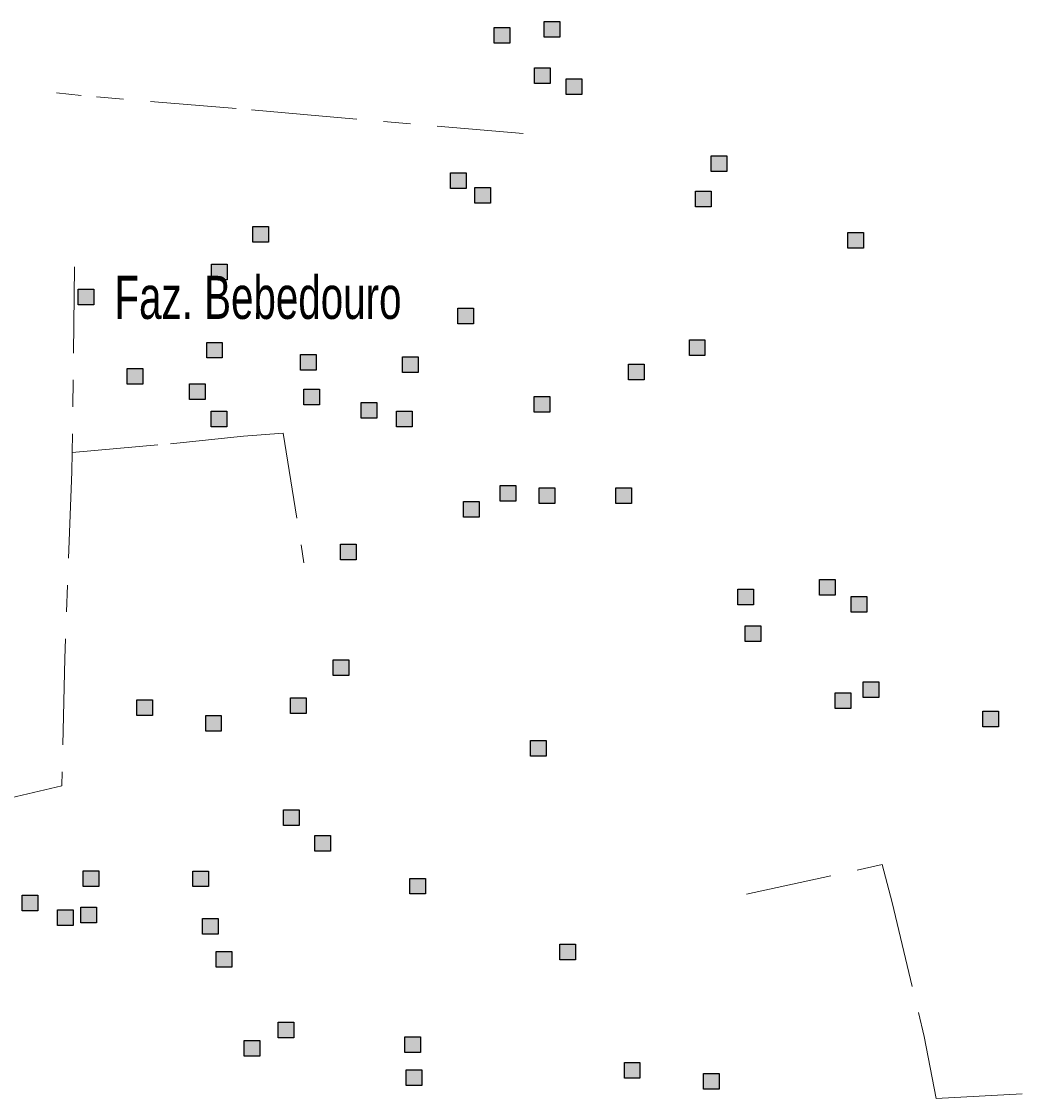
# Model space of a CAD drawing. Extents: x 445.4 to 500, y 8728.7 to 8784.
# Drawn here: x 459.662 to 463.381, y 8743.151 to 8747.148 of the extents above; entities that cross this region are included whole.
import ezdxf

# ---------------------------------------------------------------- set-up
doc = ezdxf.new("R2010")
doc.units = 0
doc.header["$LTSCALE"] = 0.064
doc.linetypes.add('DOT_DASHED', pattern=[7.7, 5, -1.2, 0.3, -1.2])
doc.layers.add('2', color=7, linetype='Continuous', lineweight=25)
doc.layers.add('22', color=7, linetype='DOT_DASHED', lineweight=13)
doc.layers.add('61', color=7, linetype='Continuous')

msp = doc.modelspace()

# ---------------------------------------------------------------- hatches: boundary and pattern name
at = {"layer": '2'}
for points in [[(461.4171, 8747.1256), (461.4751, 8747.1256), (461.4751, 8747.0676), (461.4171, 8747.0676)], [(461.6027, 8747.1482), (461.6607, 8747.1482), (461.6607, 8747.0902), (461.6027, 8747.0902)], [(461.5665, 8746.9762), (461.6245, 8746.9762), (461.6245, 8746.9182), (461.5665, 8746.9182)], [(461.6841, 8746.9354), (461.7421, 8746.9354), (461.7421, 8746.8774), (461.6841, 8746.8774)], [(462.2226, 8746.6502), (462.2806, 8746.6502), (462.2806, 8746.5922), (462.2226, 8746.5922)], [(461.2542, 8746.5868), (461.3122, 8746.5868), (461.3122, 8746.5288), (461.2542, 8746.5288)], [(461.3447, 8746.5325), (461.4027, 8746.5325), (461.4027, 8746.4745), (461.3447, 8746.4745)], [(462.1638, 8746.5189), (462.2218, 8746.5189), (462.2218, 8746.4609), (462.1638, 8746.4609)], [(460.5212, 8746.3876), (460.5792, 8746.3876), (460.5792, 8746.3296), (460.5212, 8746.3296)], [(462.7294, 8746.365), (462.7874, 8746.365), (462.7874, 8746.307), (462.7294, 8746.307)], [(460.3673, 8746.2472), (460.4253, 8746.2472), (460.4253, 8746.1892), (460.3673, 8746.1892)], [(459.8727, 8746.1543), (459.9307, 8746.1543), (459.9307, 8746.0963), (459.8727, 8746.0963)], [(461.2814, 8746.0843), (461.3394, 8746.0843), (461.3394, 8746.0263), (461.2814, 8746.0263)], [(460.3492, 8745.9575), (460.4072, 8745.9575), (460.4072, 8745.8995), (460.3492, 8745.8995)], [(462.1411, 8745.9665), (462.1991, 8745.9665), (462.1991, 8745.9085), (462.1411, 8745.9085)], [(460.6977, 8745.9122), (460.7557, 8745.9122), (460.7557, 8745.8542), (460.6977, 8745.8542)], [(461.0764, 8745.9032), (461.1344, 8745.9032), (461.1344, 8745.8452), (461.0764, 8745.8452)], [(461.9149, 8745.876), (461.9729, 8745.876), (461.9729, 8745.818), (461.9149, 8745.818)], [(460.0537, 8745.8601), (460.1117, 8745.8601), (460.1117, 8745.8021), (460.0537, 8745.8021)], [(460.2859, 8745.8036), (460.3439, 8745.8036), (460.3439, 8745.7456), (460.2859, 8745.7456)], [(460.7099, 8745.7837), (460.7679, 8745.7837), (460.7679, 8745.7257), (460.7099, 8745.7257)], [(461.5651, 8745.7565), (461.6231, 8745.7565), (461.6231, 8745.6985), (461.5651, 8745.6985)], [(460.9225, 8745.7339), (460.9805, 8745.7339), (460.9805, 8745.6759), (460.9225, 8745.6759)], [(460.366, 8745.7022), (460.424, 8745.7022), (460.424, 8745.6442), (460.366, 8745.6442)], [(461.0538, 8745.7022), (461.1118, 8745.7022), (461.1118, 8745.6442), (461.0538, 8745.6442)], [(461.4384, 8745.426), (461.4964, 8745.426), (461.4964, 8745.368), (461.4384, 8745.368)], [(461.5832, 8745.417), (461.6412, 8745.417), (461.6412, 8745.359), (461.5832, 8745.359)], [(461.8683, 8745.417), (461.9263, 8745.417), (461.9263, 8745.359), (461.8683, 8745.359)], [(461.3026, 8745.3671), (461.3606, 8745.3671), (461.3606, 8745.3091), (461.3026, 8745.3091)], [(460.8456, 8745.2087), (460.9036, 8745.2087), (460.9036, 8745.1507), (460.8456, 8745.1507)], [(462.6239, 8745.0774), (462.6819, 8745.0774), (462.6819, 8745.0194), (462.6239, 8745.0194)], [(462.3208, 8745.0412), (462.3788, 8745.0412), (462.3788, 8744.9832), (462.3208, 8744.9832)], [(462.7416, 8745.014), (462.7996, 8745.014), (462.7996, 8744.956), (462.7416, 8744.956)], [(462.3479, 8744.9053), (462.4059, 8744.9053), (462.4059, 8744.8473), (462.3479, 8744.8473)], [(460.8185, 8744.7786), (460.8765, 8744.7786), (460.8765, 8744.7206), (460.8185, 8744.7206)], [(462.7868, 8744.6971), (462.8448, 8744.6971), (462.8448, 8744.6391), (462.7868, 8744.6391)], [(460.6601, 8744.6382), (460.7181, 8744.6382), (460.7181, 8744.5802), (460.6601, 8744.5802)], [(462.6828, 8744.6563), (462.7408, 8744.6563), (462.7408, 8744.5983), (462.6828, 8744.5983)], [(460.0899, 8744.6304), (460.1479, 8744.6304), (460.1479, 8744.5724), (460.0899, 8744.5724)], [(460.3455, 8744.5728), (460.4035, 8744.5728), (460.4035, 8744.5148), (460.3455, 8744.5148)], [(463.2303, 8744.5884), (463.2883, 8744.5884), (463.2883, 8744.5304), (463.2303, 8744.5304)], [(461.5515, 8744.4798), (461.6095, 8744.4798), (461.6095, 8744.4218), (461.5515, 8744.4218)], [(460.6343, 8744.2222), (460.6923, 8744.2222), (460.6923, 8744.1642), (460.6343, 8744.1642)], [(460.7506, 8744.1266), (460.8086, 8744.1266), (460.8086, 8744.0686), (460.7506, 8744.0686)], [(459.8908, 8743.9965), (459.9488, 8743.9965), (459.9488, 8743.9385), (459.8908, 8743.9385)], [(460.2981, 8743.9953), (460.3561, 8743.9953), (460.3561, 8743.9373), (460.2981, 8743.9373)], [(461.1035, 8743.9682), (461.1615, 8743.9682), (461.1615, 8743.9102), (461.1035, 8743.9102)], [(459.6646, 8743.906), (459.7226, 8743.906), (459.7226, 8743.848), (459.6646, 8743.848)], [(459.7958, 8743.8516), (459.8538, 8743.8516), (459.8538, 8743.7936), (459.7958, 8743.7936)], [(459.8818, 8743.8607), (459.9398, 8743.8607), (459.9398, 8743.8027), (459.8818, 8743.8027)], [(460.3343, 8743.8188), (460.3923, 8743.8188), (460.3923, 8743.7608), (460.3343, 8743.7608)], [(461.6601, 8743.7237), (461.7181, 8743.7237), (461.7181, 8743.6657), (461.6601, 8743.6657)], [(460.3841, 8743.6965), (460.4421, 8743.6965), (460.4421, 8743.6385), (460.3841, 8743.6385)], [(460.6148, 8743.4339), (460.6728, 8743.4339), (460.6728, 8743.3759), (460.6148, 8743.3759)], [(460.4881, 8743.366), (460.5461, 8743.366), (460.5461, 8743.308), (460.4881, 8743.308)], [(461.0854, 8743.3796), (461.1434, 8743.3796), (461.1434, 8743.3216), (461.0854, 8743.3216)], [(461.8999, 8743.2845), (461.9579, 8743.2845), (461.9579, 8743.2265), (461.8999, 8743.2265)], [(461.09, 8743.2574), (461.148, 8743.2574), (461.148, 8743.1994), (461.09, 8743.1994)], [(462.1941, 8743.2438), (462.2521, 8743.2438), (462.2521, 8743.1858), (462.1941, 8743.1858)]]:
    msp.add_hatch(color=256, dxfattribs=at).paths.add_polyline_path(points)

# ---------------------------------------------------------------- linework, layer by layer
for points in [[(461.4171, 8747.1256), (461.4751, 8747.1256), (461.4751, 8747.0676), (461.4171, 8747.0676)], [(461.6027, 8747.1482), (461.6607, 8747.1482), (461.6607, 8747.0902), (461.6027, 8747.0902)], [(461.5665, 8746.9762), (461.6245, 8746.9762), (461.6245, 8746.9182), (461.5665, 8746.9182)], [(461.6841, 8746.9354), (461.7421, 8746.9354), (461.7421, 8746.8774), (461.6841, 8746.8774)], [(462.2226, 8746.6502), (462.2806, 8746.6502), (462.2806, 8746.5922), (462.2226, 8746.5922)], [(461.2542, 8746.5868), (461.3122, 8746.5868), (461.3122, 8746.5288), (461.2542, 8746.5288)], [(461.3447, 8746.5325), (461.4027, 8746.5325), (461.4027, 8746.4745), (461.3447, 8746.4745)], [(462.1638, 8746.5189), (462.2218, 8746.5189), (462.2218, 8746.4609), (462.1638, 8746.4609)], [(460.5212, 8746.3876), (460.5792, 8746.3876), (460.5792, 8746.3296), (460.5212, 8746.3296)], [(462.7294, 8746.365), (462.7874, 8746.365), (462.7874, 8746.307), (462.7294, 8746.307)], [(460.3673, 8746.2472), (460.4253, 8746.2472), (460.4253, 8746.1892), (460.3673, 8746.1892)], [(459.8727, 8746.1543), (459.9307, 8746.1543), (459.9307, 8746.0963), (459.8727, 8746.0963)], [(461.2814, 8746.0843), (461.3394, 8746.0843), (461.3394, 8746.0263), (461.2814, 8746.0263)], [(460.3492, 8745.9575), (460.4072, 8745.9575), (460.4072, 8745.8995), (460.3492, 8745.8995)], [(462.1411, 8745.9665), (462.1991, 8745.9665), (462.1991, 8745.9085), (462.1411, 8745.9085)], [(460.6977, 8745.9122), (460.7557, 8745.9122), (460.7557, 8745.8542), (460.6977, 8745.8542)], [(461.0764, 8745.9032), (461.1344, 8745.9032), (461.1344, 8745.8452), (461.0764, 8745.8452)], [(461.9149, 8745.876), (461.9729, 8745.876), (461.9729, 8745.818), (461.9149, 8745.818)], [(460.0537, 8745.8601), (460.1117, 8745.8601), (460.1117, 8745.8021), (460.0537, 8745.8021)], [(460.2859, 8745.8036), (460.3439, 8745.8036), (460.3439, 8745.7456), (460.2859, 8745.7456)], [(460.7099, 8745.7837), (460.7679, 8745.7837), (460.7679, 8745.7257), (460.7099, 8745.7257)], [(461.5651, 8745.7565), (461.6231, 8745.7565), (461.6231, 8745.6985), (461.5651, 8745.6985)], [(460.9225, 8745.7339), (460.9805, 8745.7339), (460.9805, 8745.6759), (460.9225, 8745.6759)], [(460.366, 8745.7022), (460.424, 8745.7022), (460.424, 8745.6442), (460.366, 8745.6442)], [(461.0538, 8745.7022), (461.1118, 8745.7022), (461.1118, 8745.6442), (461.0538, 8745.6442)], [(461.4384, 8745.426), (461.4964, 8745.426), (461.4964, 8745.368), (461.4384, 8745.368)], [(461.5832, 8745.417), (461.6412, 8745.417), (461.6412, 8745.359), (461.5832, 8745.359)], [(461.8683, 8745.417), (461.9263, 8745.417), (461.9263, 8745.359), (461.8683, 8745.359)], [(461.3026, 8745.3671), (461.3606, 8745.3671), (461.3606, 8745.3091), (461.3026, 8745.3091)], [(460.8456, 8745.2087), (460.9036, 8745.2087), (460.9036, 8745.1507), (460.8456, 8745.1507)], [(462.6239, 8745.0774), (462.6819, 8745.0774), (462.6819, 8745.0194), (462.6239, 8745.0194)], [(462.3208, 8745.0412), (462.3788, 8745.0412), (462.3788, 8744.9832), (462.3208, 8744.9832)], [(462.7416, 8745.014), (462.7996, 8745.014), (462.7996, 8744.956), (462.7416, 8744.956)], [(462.3479, 8744.9053), (462.4059, 8744.9053), (462.4059, 8744.8473), (462.3479, 8744.8473)], [(460.8185, 8744.7786), (460.8765, 8744.7786), (460.8765, 8744.7206), (460.8185, 8744.7206)], [(462.7868, 8744.6971), (462.8448, 8744.6971), (462.8448, 8744.6391), (462.7868, 8744.6391)], [(460.6601, 8744.6382), (460.7181, 8744.6382), (460.7181, 8744.5802), (460.6601, 8744.5802)], [(462.6828, 8744.6563), (462.7408, 8744.6563), (462.7408, 8744.5983), (462.6828, 8744.5983)], [(460.0899, 8744.6304), (460.1479, 8744.6304), (460.1479, 8744.5724), (460.0899, 8744.5724)], [(460.3455, 8744.5728), (460.4035, 8744.5728), (460.4035, 8744.5148), (460.3455, 8744.5148)], [(463.2303, 8744.5884), (463.2883, 8744.5884), (463.2883, 8744.5304), (463.2303, 8744.5304)], [(461.5515, 8744.4798), (461.6095, 8744.4798), (461.6095, 8744.4218), (461.5515, 8744.4218)], [(460.6343, 8744.2222), (460.6923, 8744.2222), (460.6923, 8744.1642), (460.6343, 8744.1642)], [(460.7506, 8744.1266), (460.8086, 8744.1266), (460.8086, 8744.0686), (460.7506, 8744.0686)], [(459.8908, 8743.9965), (459.9488, 8743.9965), (459.9488, 8743.9385), (459.8908, 8743.9385)], [(460.2981, 8743.9953), (460.3561, 8743.9953), (460.3561, 8743.9373), (460.2981, 8743.9373)], [(461.1035, 8743.9682), (461.1615, 8743.9682), (461.1615, 8743.9102), (461.1035, 8743.9102)], [(459.6646, 8743.906), (459.7226, 8743.906), (459.7226, 8743.848), (459.6646, 8743.848)], [(459.7958, 8743.8516), (459.8538, 8743.8516), (459.8538, 8743.7936), (459.7958, 8743.7936)], [(459.8818, 8743.8607), (459.9398, 8743.8607), (459.9398, 8743.8027), (459.8818, 8743.8027)], [(460.3343, 8743.8188), (460.3923, 8743.8188), (460.3923, 8743.7608), (460.3343, 8743.7608)], [(461.6601, 8743.7237), (461.7181, 8743.7237), (461.7181, 8743.6657), (461.6601, 8743.6657)], [(460.3841, 8743.6965), (460.4421, 8743.6965), (460.4421, 8743.6385), (460.3841, 8743.6385)], [(460.6148, 8743.4339), (460.6728, 8743.4339), (460.6728, 8743.3759), (460.6148, 8743.3759)], [(460.4881, 8743.366), (460.5461, 8743.366), (460.5461, 8743.308), (460.4881, 8743.308)], [(461.0854, 8743.3796), (461.1434, 8743.3796), (461.1434, 8743.3216), (461.0854, 8743.3216)], [(461.8999, 8743.2845), (461.9579, 8743.2845), (461.9579, 8743.2265), (461.8999, 8743.2265)], [(461.09, 8743.2574), (461.148, 8743.2574), (461.148, 8743.1994), (461.09, 8743.1994)], [(462.1941, 8743.2438), (462.2521, 8743.2438), (462.2521, 8743.1858), (462.1941, 8743.1858)]]:
    msp.add_lwpolyline(points, close=True, dxfattribs=at)
at = {"layer": '22'}
msp.add_line((459.8591, 8746.2378), (459.8496, 8745.5488), dxfattribs=at)
for points in [[(461.5243, 8746.7329), (460.8346, 8746.7923), (460.459, 8746.8252), (459.8839, 8746.8731), (459.7923, 8746.8838)], [(459.8496, 8745.5488), (460.215, 8745.5809), (460.4863, 8745.6098), (460.6334, 8745.6209), (460.7104, 8745.1389)], [(459.8496, 8745.5488), (459.8486, 8745.4764), (459.8221, 8744.7839), (459.8119, 8744.3114), (459.5787, 8744.2572), (459.2664, 8744.199), (459.0403, 8744.1602)], [(462.3533, 8743.9098), (462.8567, 8744.0193), (462.8938, 8743.8783), (463.0127, 8743.3812), (463.0573, 8743.1512), (463.8745, 8743.1957), (464.2447, 8743.1963)]]:
    msp.add_lwpolyline(points, dxfattribs=at)

# ---------------------------------------------------------------- texts
at = {"layer": '61', "width": 0.7}
msp.add_text('Faz. Bebedouro', height=0.16, dxfattribs=at).set_placement((460.0068, 8746.0445))

doc.saveas('drawing.dxf')
